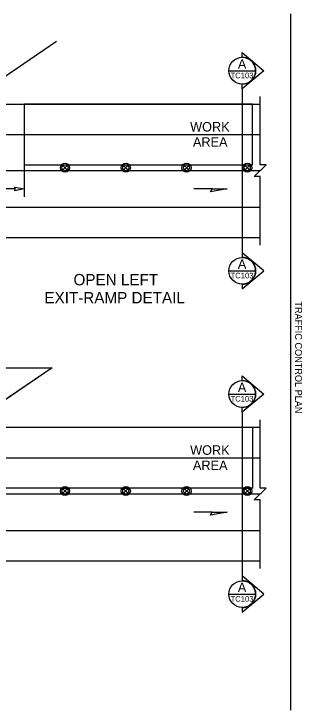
# Model space of a CAD drawing. Extents: x 99999 to 100116, y 99995 to 100013.
# Drawn here: x 100064.96 to 100068, y 100001.58 to 100008.92 of the extents above; entities that cross this region are included whole.
import ezdxf

# ---------------------------------------------------------------- set-up
doc = ezdxf.new("R2010")
doc.units = 0
for name, color, linetype in [('RD_MK_LineEdgeYellow', 7, 'Continuous'), ('RD_MK_LineLane', 7, 'Continuous'), ('SH_DE_DetailHeading2Text', 7, 'Continuous'), ('SH_TI_WZSectionCut', 7, 'Continuous'), ('TR_WZ_TrafficSafetyDrum', 7, 'Continuous'), ('TR_WZ_WorkAreaLabel', 7, 'Continuous'), ('TR_WZ_WorkZoneDetails', 7, 'Continuous')]:
    doc.layers.add(name, color=color, linetype=linetype)

msp = doc.modelspace()

# ---------------------------------------------------------------- linework, layer by layer
at = {"layer": 'RD_MK_LineEdgeYellow'}
for p, q in [((100064.4388, 100007.648), (100067.555, 100007.648)), ((100060.32, 100006.88), (100067.555, 100006.88)), ((100064.4388, 100004.238), (100067.555, 100004.238)), ((100060.32, 100003.47), (100067.555, 100003.47))]:
    msp.add_line(p, q, dxfattribs=at)
at = {"layer": 'RD_MK_LineLane'}
for points in [[(100067.555, 100007.264), (100060.32, 100007.264)], [(100067.555, 100003.854), (100060.32, 100003.854)]]:
    msp.add_lwpolyline(points, dxfattribs=at)
at = {"layer": 'SH_TI_WZSectionCut'}
for p, q in [((100067.3657, 100008.4604), (100067.3657, 100008.5103)), ((100067.3657, 100008.5103), (100067.5938, 100008.3192)), ((100067.5938, 100008.3192), (100067.3657, 100008.128)), ((100067.3657, 100008.128), (100067.3657, 100008.1779)), ((100067.3657, 100008.128), (100067.3657, 100006.4)), ((100067.3657, 100006.4), (100067.3657, 100006.3501)), ((100067.5939, 100006.2089), (100067.3657, 100006.4)), ((100067.3657, 100006.0178), (100067.5939, 100006.2089)), ((100067.3657, 100006.0677), (100067.3657, 100006.0178)), ((100067.3657, 100005.0503), (100067.3657, 100005.1002)), ((100067.3657, 100005.1002), (100067.5938, 100004.9091)), ((100067.5938, 100004.9091), (100067.3657, 100004.718)), ((100067.3657, 100004.718), (100067.3657, 100004.7679)), ((100067.3657, 100004.718), (100067.3657, 100002.99)), ((100067.3657, 100002.99), (100067.3657, 100002.94)), ((100067.5939, 100002.7988), (100067.3657, 100002.99)), ((100067.3657, 100002.6077), (100067.5939, 100002.7988)), ((100067.3657, 100002.6576), (100067.3657, 100002.6077))]:
    msp.add_line(p, q, dxfattribs=at)
for points in [[(100067.2245, 100008.3192), (100067.5069, 100008.3192)], [(100067.2245, 100006.2089), (100067.5069, 100006.2089)], [(100067.2245, 100004.9091), (100067.5069, 100004.9091)], [(100067.2245, 100002.7988), (100067.5069, 100002.7988)]]:
    msp.add_lwpolyline(points, dxfattribs=at)
for centre in [(100067.3657, 100008.3192), (100067.3657, 100006.2089), (100067.3657, 100004.9091), (100067.3657, 100002.7988)]:
    msp.add_circle(centre, 0.1412, dxfattribs=at)
for centre in [(100067.3657, 100008.3192), (100067.3657, 100006.2089), (100067.3657, 100004.9091), (100067.3657, 100002.7988)]:
    msp.add_arc(centre, 0.1412, 269.99779, 90.00221, dxfattribs=at)
at = {"layer": 'TR_WZ_TrafficSafetyDrum'}
for p, q in [((100065.4763, 100007.2734), (100065.5215, 100007.3186)), ((100065.5215, 100007.2734), (100065.4763, 100007.3186)), ((100066.1163, 100007.2734), (100066.1615, 100007.3186)), ((100066.1615, 100007.2734), (100066.1163, 100007.3186)), ((100066.7563, 100007.2734), (100066.8015, 100007.3186)), ((100066.8015, 100007.2734), (100066.7563, 100007.3186)), ((100067.3963, 100007.2734), (100067.4415, 100007.3186)), ((100067.4415, 100007.2734), (100067.3963, 100007.3186)), ((100065.4763, 100003.8633), (100065.5215, 100003.9086)), ((100065.5215, 100003.8633), (100065.4763, 100003.9086)), ((100066.1163, 100003.8633), (100066.1615, 100003.9086)), ((100066.1615, 100003.8633), (100066.1163, 100003.9086)), ((100066.7563, 100003.8633), (100066.8015, 100003.9086)), ((100066.8015, 100003.8633), (100066.7563, 100003.9086)), ((100067.3963, 100003.8633), (100067.4415, 100003.9086)), ((100067.4415, 100003.8633), (100067.3963, 100003.9086))]:
    msp.add_line(p, q, dxfattribs=at)
for centre, radius in [((100065.4989, 100007.296), 0.048), ((100065.4989, 100007.296), 0.048), ((100065.4989, 100007.296), 0.032), ((100066.1389, 100007.296), 0.048), ((100066.1389, 100007.296), 0.048), ((100066.1389, 100007.296), 0.032), ((100066.7789, 100007.296), 0.048), ((100066.7789, 100007.296), 0.048), ((100066.7789, 100007.296), 0.032), ((100067.4189, 100007.296), 0.048), ((100067.4189, 100007.296), 0.048), ((100067.4189, 100007.296), 0.032), ((100065.4989, 100003.886), 0.048), ((100065.4989, 100003.886), 0.048), ((100065.4989, 100003.886), 0.032), ((100066.1389, 100003.886), 0.048), ((100066.1389, 100003.886), 0.048), ((100066.1389, 100003.886), 0.032), ((100066.7789, 100003.886), 0.048), ((100066.7789, 100003.886), 0.048), ((100066.7789, 100003.886), 0.032), ((100067.4189, 100003.886), 0.048), ((100067.4189, 100003.886), 0.048), ((100067.4189, 100003.886), 0.032)]:
    msp.add_circle(centre, radius, dxfattribs=at)
at = {"layer": 'TR_WZ_WorkZoneDetails'}
for p, q in [((100067.875, 100008.9181), (100067.875, 100001.5759)), ((100065.409, 100008.626), (100064.4388, 100007.968)), ((100064.4388, 100007.968), (100067.555, 100007.968)), ((100065.0668, 100007.328), (100065.0668, 100006.9906)), ((100064.973, 100007.072), (100064.8628, 100007.072)), ((100067.0492, 100007.072), (100066.8563, 100007.072)), ((100060.32, 100006.56), (100067.555, 100006.56)), ((100065.3633, 100005.1849), (100064.4388, 100004.558)), ((100064.4388, 100004.558), (100067.555, 100004.558)), ((100067.0492, 100003.662), (100066.8563, 100003.662)), ((100060.32, 100003.15), (100067.555, 100003.15))]:
    msp.add_line(p, q, dxfattribs=at)
for points in [[(100067.555, 100006.48), (100067.555, 100007.2021), (100067.491, 100007.2021), (100067.619, 100007.326), (100067.555, 100007.326), (100067.555, 100008.048)], [(100067.555, 100003.07), (100067.555, 100003.792), (100067.491, 100003.792), (100067.619, 100003.9159), (100067.555, 100003.9159), (100067.555, 100004.638)]]:
    msp.add_lwpolyline(points, dxfattribs=at)
for points in [[(100065.0668, 100007.968), (100065.0668, 100007.328), (100067.475, 100007.328), (100067.475, 100007.968)], [(100065.0668, 100007.072), (100064.9685, 100007.0528), (100064.973, 100007.072), (100064.9685, 100007.0913)], [(100067.2065, 100007.072), (100067.0314, 100007.0412), (100067.0492, 100007.072)], [(100060.4, 100004.558), (100062.9559, 100004.558), (100063.8809, 100005.1849), (100065.3633, 100005.1849), (100064.4388, 100004.558), (100065.8504, 100004.558), (100067.475, 100004.558), (100067.475, 100003.918), (100060.4, 100003.918)], [(100067.2065, 100003.662), (100067.0314, 100003.6311), (100067.0492, 100003.662)]]:
    msp.add_lwpolyline(points, close=True, dxfattribs=at)

# ---------------------------------------------------------------- texts
at = {"layer": 'SH_DE_DetailHeading2Text'}
for s, p in [('OPEN LEFT', (100065.5881, 100006.0554)), ('EXIT-RAMP DETAIL', (100065.2814, 100005.8654))]:
    msp.add_text(s, height=0.12, rotation=360, dxfattribs=at).set_placement(p)
at = {"layer": 'SH_TI_WZSectionCut'}
for s, height, rotation, p in [('A', 0.1, 0.00995, (100067.3195, 100008.3398)), ('TC103', 0.06, 360, (100067.243, 100008.2392)), ('A', 0.1, 0.00995, (100067.3195, 100006.2295)), ('TC103', 0.06, 360, (100067.243, 100006.1289)), ('A', 0.1, 0.00995, (100067.3195, 100004.9297)), ('TC103', 0.06, 360, (100067.243, 100004.8291)), ('A', 0.1, 0.00995, (100067.3195, 100002.8195)), ('TC103', 0.06, 360, (100067.243, 100002.7188))]:
    msp.add_text(s, height=height, rotation=rotation, dxfattribs=at).set_placement(p)
at = {"layer": 'TR_WZ_WorkAreaLabel'}
for s, p in [('WORK', (100066.8169, 100007.678)), ('AREA', (100066.8465, 100007.518)), ('WORK', (100066.8169, 100004.268)), ('AREA', (100066.8465, 100004.108))]:
    msp.add_text(s, height=0.1, dxfattribs=at).set_placement(p)
at = {"layer": 'TR_WZ_WorkZoneDetails'}
msp.add_text('TRAFFIC CONTROL PLAN', height=0.072, rotation=270, dxfattribs=at).set_placement((100067.923, 100005.8862))

doc.saveas('drawing.dxf')
